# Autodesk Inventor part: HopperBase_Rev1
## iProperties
Created: 2009-01
Part Number: HopperBase_Rev1
Document SubType Name: Modeling
Designer: claivier
Material: Acier galvanisé
Norme de conversion: STEP AP214IS
Nom du fichier: HopperBase_Rev1.STEP
Préprocesseur: SolidWorks 2008
Postprocesseur: Build: 344a, Release: 11 SP2 - Date: Fri 08/18/2006
Unités envoyées: INCHES
Incertitude: 1e-05
Author: claivier
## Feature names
1. Base1
2. Extrusion1
